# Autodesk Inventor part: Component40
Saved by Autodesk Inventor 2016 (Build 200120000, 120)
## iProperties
Created: 2016-09
Part Number: Component40
Material: Generic
Document SubType Name: Modeling
Designer: Administrator
Appearance: Generic
Author: Administrator
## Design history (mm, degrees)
feature "Body2"
body "Solid1"
